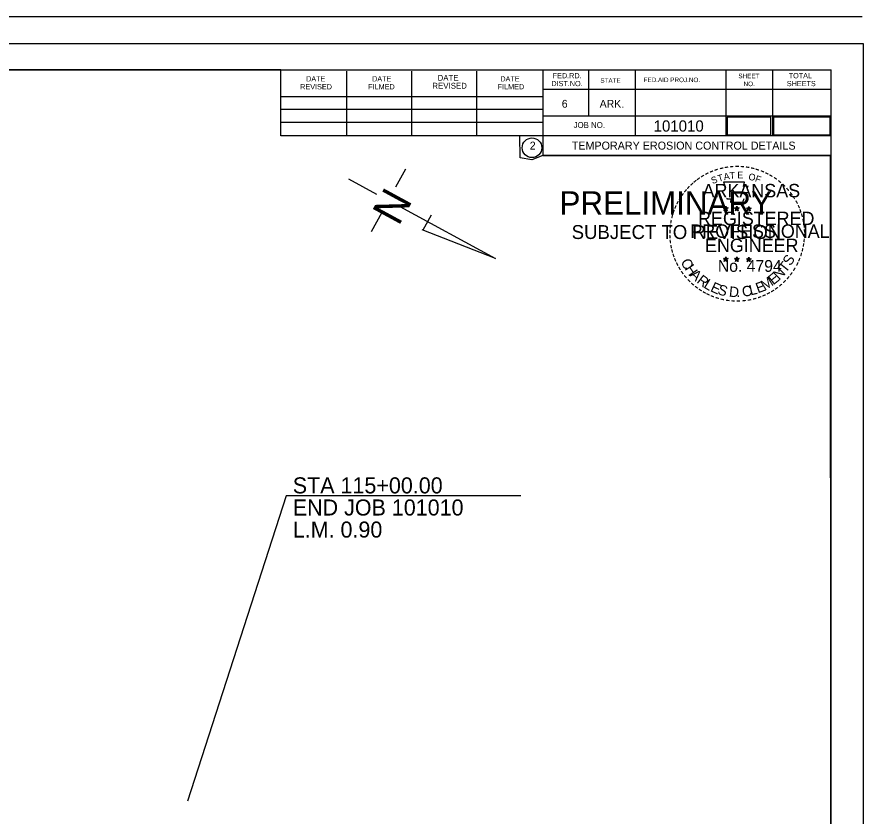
# Model space of a CAD drawing. Extents: x 7675 to 14104, y 9961 to 11168.
# Drawn here: x 9203 to 9835, y 10470 to 11067 of the extents above; entities that cross this region are included whole.
import ezdxf

# ---------------------------------------------------------------- set-up
doc = ezdxf.new("R2010")
doc.units = 0
for name, color, linetype in [('C-PSVP', 7, 'Continuous'), ('Clearing and Grubbing Ditch Checks', 7, 'Continuous'), ('Clearing and Grubbing Silt Fence', 7, 'Continuous'), ('Clearing and Grubbing Temp Seeding', 7, 'Continuous'), ('GREEN_TXT', 7, 'Continuous'), ('SEAL-INFO', 7, 'Continuous'), ('SIGNATURE', 7, 'Continuous'), ('Stage 1 Construction', 7, 'Continuous'), ('Stage 1 Ditch Checks', 7, 'Continuous')]:
    doc.layers.add(name, color=color, linetype=linetype)

msp = doc.modelspace()

# ---------------------------------------------------------------- linework, layer by layer
for p, q in [((9493.53, 10953.13), (9486.17, 10939.57)), ((9450.84, 10945.87), (9471.86, 10934.46)), ((9489.19, 10925.04), (9560.68, 10886.21)), ((9475.86, 10920.6), (9467.99, 10906.11)), ((9512.62, 10918.74), (9506.45, 10907.38)), ((9560.68, 10886.21), (9506.07, 10907.59))]:
    msp.add_line(p, q)
at = {"layer": 'C-PSVP'}
for p, q in [((9730.98, 10924.04), (9732.73, 10923.49)), ((9730.98, 10924.04), (9732.25, 10923.82)), ((9730.98, 10924.04), (9732.17, 10923.43)), ((9731.65, 10922), (9732.73, 10923.49)), ((9731.65, 10922), (9732.28, 10923.22)), ((9731.65, 10922), (9732.72, 10923.09)), ((9732.73, 10925.31), (9732.52, 10924.05)), ((9733.79, 10922), (9732.72, 10923.07)), ((9732.73, 10923.49), (9732.73, 10925.31)), ((9732.73, 10925.31), (9732.97, 10924.06)), ((9734.46, 10924.04), (9732.73, 10923.49)), ((9733.79, 10922), (9732.73, 10923.49)), ((9734.46, 10924.04), (9733.03, 10923.8)), ((9733.79, 10922), (9733.11, 10923.46)), ((9734.46, 10924.04), (9733.44, 10923.53)), ((9739.33, 10924.04), (9741.08, 10923.49)), ((9739.33, 10924.04), (9740.6, 10923.82)), ((9739.33, 10924.04), (9740.52, 10923.43)), ((9740, 10922), (9741.08, 10923.49)), ((9740, 10922), (9740.63, 10923.22)), ((9740, 10922), (9741.07, 10923.09)), ((9741.08, 10925.31), (9740.87, 10924.05)), ((9742.14, 10922), (9741.07, 10923.07)), ((9741.08, 10923.49), (9741.08, 10925.31)), ((9741.08, 10925.31), (9741.32, 10924.06)), ((9742.81, 10924.04), (9741.08, 10923.49)), ((9742.14, 10922), (9741.08, 10923.49)), ((9742.81, 10924.04), (9741.38, 10923.8)), ((9742.14, 10922), (9741.46, 10923.46)), ((9742.81, 10924.04), (9741.79, 10923.53)), ((9748.15, 10923.98), (9749.9, 10923.43)), ((9748.15, 10923.98), (9749.42, 10923.76)), ((9748.15, 10923.98), (9749.34, 10923.37)), ((9748.82, 10921.94), (9749.9, 10923.43)), ((9748.82, 10921.94), (9749.45, 10923.16)), ((9748.82, 10921.94), (9749.89, 10923.03)), ((9749.9, 10925.25), (9749.69, 10923.99)), ((9750.96, 10921.94), (9749.89, 10923.01)), ((9749.9, 10923.43), (9749.9, 10925.25)), ((9749.9, 10925.25), (9750.14, 10924)), ((9751.63, 10923.98), (9749.9, 10923.43)), ((9750.96, 10921.94), (9749.9, 10923.43)), ((9751.63, 10923.98), (9750.2, 10923.74)), ((9750.96, 10921.94), (9750.28, 10923.4)), ((9751.63, 10923.98), (9750.61, 10923.47)), ((9730.96, 10886.18), (9732.71, 10885.62)), ((9730.96, 10886.18), (9732.23, 10885.95)), ((9730.96, 10886.18), (9732.15, 10885.57)), ((9731.63, 10884.14), (9732.71, 10885.62)), ((9731.63, 10884.14), (9732.26, 10885.36)), ((9731.63, 10884.14), (9732.7, 10885.22)), ((9732.71, 10887.45), (9732.5, 10886.19)), ((9733.77, 10884.14), (9732.7, 10885.21)), ((9732.71, 10885.62), (9732.71, 10887.45)), ((9732.71, 10887.45), (9732.95, 10886.2)), ((9734.44, 10886.18), (9732.71, 10885.62)), ((9733.77, 10884.14), (9732.71, 10885.62)), ((9734.44, 10886.18), (9733.01, 10885.93)), ((9733.77, 10884.14), (9733.09, 10885.59)), ((9734.44, 10886.18), (9733.42, 10885.67)), ((9739.31, 10886.18), (9741.05, 10885.62)), ((9739.31, 10886.18), (9740.57, 10885.95)), ((9739.31, 10886.18), (9740.49, 10885.57)), ((9739.97, 10884.14), (9741.05, 10885.62)), ((9739.97, 10884.14), (9740.6, 10885.36)), ((9739.97, 10884.14), (9741.04, 10885.22)), ((9741.05, 10887.45), (9740.85, 10886.19)), ((9742.12, 10884.14), (9741.04, 10885.21)), ((9741.05, 10885.62), (9741.05, 10887.45)), ((9741.05, 10887.45), (9741.3, 10886.2)), ((9742.79, 10886.18), (9741.05, 10885.62)), ((9742.12, 10884.14), (9741.05, 10885.62)), ((9742.79, 10886.18), (9741.36, 10885.93)), ((9742.12, 10884.14), (9741.43, 10885.59)), ((9742.79, 10886.18), (9741.77, 10885.67)), ((9748.14, 10886.13), (9749.89, 10885.57)), ((9748.14, 10886.13), (9749.41, 10885.9)), ((9748.14, 10886.13), (9749.33, 10885.52)), ((9748.81, 10884.09), (9749.89, 10885.57)), ((9748.81, 10884.09), (9749.44, 10885.31)), ((9748.81, 10884.09), (9749.88, 10885.17)), ((9749.89, 10887.4), (9749.68, 10886.14)), ((9750.95, 10884.09), (9749.88, 10885.16)), ((9749.89, 10885.57), (9749.89, 10887.4)), ((9749.89, 10887.4), (9750.13, 10886.15)), ((9751.62, 10886.13), (9749.89, 10885.57)), ((9750.95, 10884.09), (9749.89, 10885.57)), ((9751.62, 10886.13), (9750.19, 10885.88)), ((9750.95, 10884.09), (9750.27, 10885.54)), ((9751.62, 10886.13), (9750.6, 10885.62))]:
    msp.add_line(p, q, dxfattribs=at)
for points in [[(9731.19, 10943.43), (9732.53, 10939.3)], [(9748.74, 10938.82), (9749.45, 10940.24), (9746.03, 10940.12), (9746.77, 10943.43), (9731.19, 10943.43)], [(9733.65, 10931.32), (9733.65, 10930.88), (9736.46, 10930.79), (9736.19, 10928.42), (9745.54, 10928.42), (9746.55, 10931.1)], [(9732.73, 10925.31), (9733.79, 10922), (9730.98, 10924.04), (9734.46, 10924.04), (9731.65, 10922), (9732.73, 10925.31)], [(9741.08, 10925.31), (9742.14, 10922), (9739.33, 10924.04), (9742.81, 10924.04), (9740, 10922), (9741.08, 10925.31)], [(9749.9, 10925.25), (9750.96, 10921.94), (9748.15, 10923.98), (9751.63, 10923.98), (9748.82, 10921.94), (9749.9, 10925.25)], [(9732.71, 10887.45), (9733.77, 10884.14), (9730.96, 10886.18), (9734.44, 10886.18), (9731.63, 10884.14), (9732.71, 10887.45)], [(9741.05, 10887.45), (9742.12, 10884.14), (9739.31, 10886.18), (9742.79, 10886.18), (9739.97, 10884.14), (9741.05, 10887.45)], [(9749.89, 10887.4), (9750.95, 10884.09), (9748.14, 10886.13), (9751.62, 10886.13), (9748.81, 10884.09), (9749.89, 10887.4)]]:
    msp.add_lwpolyline(points, dxfattribs=at)
for centre, radius in [((9732.72, 10923.48), 0.861), ((9732.72, 10923.48), 0.723), ((9732.72, 10923.48), 0.579), ((9732.72, 10923.48), 0.495), ((9732.72, 10923.48), 0.374), ((9732.72, 10923.48), 0.248), ((9732.72, 10923.48), 0.148), ((9741.07, 10923.48), 0.861), ((9741.07, 10923.48), 0.723), ((9741.07, 10923.48), 0.579), ((9741.07, 10923.48), 0.495), ((9741.07, 10923.48), 0.374), ((9741.07, 10923.48), 0.248), ((9741.07, 10923.48), 0.148), ((9749.89, 10923.42), 0.861), ((9749.89, 10923.42), 0.723), ((9749.89, 10923.42), 0.579), ((9749.89, 10923.42), 0.495), ((9749.89, 10923.42), 0.374), ((9749.89, 10923.42), 0.248), ((9749.89, 10923.42), 0.148), ((9732.7, 10885.62), 0.861), ((9732.7, 10885.62), 0.723), ((9732.7, 10885.62), 0.579), ((9732.7, 10885.62), 0.495), ((9732.7, 10885.62), 0.374), ((9732.7, 10885.62), 0.248), ((9732.7, 10885.62), 0.148), ((9741.05, 10885.62), 0.861), ((9741.05, 10885.62), 0.723), ((9741.05, 10885.62), 0.579), ((9741.05, 10885.62), 0.495), ((9741.05, 10885.62), 0.374), ((9741.05, 10885.62), 0.248), ((9741.05, 10885.62), 0.148), ((9749.88, 10885.57), 0.861), ((9749.88, 10885.57), 0.723), ((9749.88, 10885.57), 0.579), ((9749.88, 10885.57), 0.495), ((9749.88, 10885.57), 0.374), ((9749.88, 10885.57), 0.248), ((9749.88, 10885.57), 0.148)]:
    msp.add_circle(centre, radius, dxfattribs=at)
at = {"layer": 'Clearing and Grubbing Ditch Checks'}
msp.add_lwpolyline([(9733.9, 10978.65), (9766.55, 10978.65), (9766.55, 10991.85), (9733.9, 10991.85)], close=True, dxfattribs=at)
at = {"layer": 'Clearing and Grubbing Silt Fence'}
msp.add_lwpolyline([(9768.39, 10978.65), (9810.76, 10978.65), (9810.76, 10991.85), (9768.39, 10991.85)], close=True, dxfattribs=at)
at = {"layer": 'GREEN_TXT'}
for p, q in [((9834.58, 11066.7), (8074.58, 11066.7)), ((8230.68, 11027.3), (9811.58, 11027.3)), ((9400.28, 10977.9), (9400.28, 11027.3)), ((9449.58, 10977.9), (9449.58, 11026.3)), ((9498.38, 10977.9), (9498.38, 11026.3)), ((9546.78, 10977.9), (9546.78, 11026.3)), ((9596.08, 11027.3), (9596.08, 10963.3)), ((9630.28, 11027.3), (9630.28, 10992.6)), ((9664.98, 11027.3), (9664.98, 10977.9)), ((9732.88, 11027.3), (9732.88, 10977.9)), ((9767.58, 11027.3), (9767.58, 10977.9)), ((9811.58, 10000), (9811.58, 11027.3)), ((9811.58, 11012.6), (9596.08, 11012.6)), ((9811.58, 11012.7), (9811.58, 11012.7)), ((9400.28, 11007.2), (9596.08, 11007.2)), ((9400.28, 10997.9), (9596.08, 10997.9)), ((9811.58, 10992.6), (9596.08, 10992.6)), ((9400.28, 10988.2), (9596.08, 10988.2)), ((9811.58, 10977.9), (9400.28, 10977.9)), ((9596.08, 10963.3), (9811.58, 10963.3))]:
    msp.add_line(p, q, dxfattribs=at)
msp.add_circle((9588.01, 10968.98), 7.33, dxfattribs=at)
at = {"layer": 'SEAL-INFO'}
msp.add_lwpolyline([(8168.64, 11046.77), (9835.34, 11046.77), (9835.34, 9980.09), (8168.64, 9980.09)], close=True, dxfattribs=at)
at = {"layer": 'Stage 1 Construction'}
msp.add_lwpolyline([(9579.58, 10709.13), (9404.35, 10709.13), (9330.67, 10480.99)], dxfattribs=at)
at = {"layer": 'Stage 1 Ditch Checks'}
msp.add_lwpolyline([(8230.68, 10000), (9811.58, 10000), (9810.97, 10963.3), (9596.08, 10963.3), (9587.98, 10959.87), (9579.17, 10961.4), (9578.94, 10977.9), (9400.28, 10977.9), (9400.28, 11027.3), (8230.68, 11027.3)], close=True, dxfattribs=at)
msp.add_lwpolyline([(8230.68, 10000), (9811.58, 10000), (9810.97, 10963.3), (9596.08, 10963.3), (9587.98, 10959.87), (9579.17, 10961.4), (9578.94, 10977.9), (9400.28, 10977.9), (9400.28, 11027.3), (8230.68, 11027.3)], close=True, dxfattribs=at)
msp.add_lwpolyline([(8230.68, 10000), (9811.58, 10000), (9810.97, 10963.3), (9596.08, 10963.3), (9587.98, 10959.87), (9579.17, 10961.4), (9578.94, 10977.9), (9400.28, 10977.9), (9400.28, 11027.3), (8230.68, 11027.3)], close=True, dxfattribs=at)
msp.add_lwpolyline([(8230.68, 10000), (9811.58, 10000), (9810.97, 10963.3), (9596.08, 10963.3), (9587.98, 10959.87), (9579.17, 10961.4), (9578.94, 10977.9), (9400.28, 10977.9), (9400.28, 11027.3), (8230.68, 11027.3)], close=True, dxfattribs=at)
msp.add_lwpolyline([(8230.68, 10000), (9811.58, 10000), (9810.97, 10963.3), (9596.08, 10963.3), (9587.98, 10959.87), (9579.17, 10961.4), (9578.94, 10977.9), (9400.28, 10977.9), (9400.28, 11027.3), (8230.68, 11027.3)], close=True, dxfattribs=at)

# ---------------------------------------------------------------- texts
msp.add_text('N', height=23.27, rotation=241.48958).set_placement((9478.67, 10940.8))
at = {"layer": 'C-PSVP'}
for s, height, rotation, p in [('-', 8, 13.63015, (9728.68, 10950.27)), ('-', 8, 10.21935, (9732.07, 10951.08)), ('-', 8, 5.89682, (9735.71, 10951.63)), ('-', 8, 0.18623, (9739.57, 10951.99)), ('-', 8, 357.74304, (9743.19, 10951.93)), ('-', 8, 352.16172, (9746.91, 10951.65)), ('-', 8, 347.20489, (9750.5, 10951.08)), ('-', 8, 34.06357, (9715.61, 10944.29)), ('-', 8, 28.79182, (9718.59, 10946.14)), ('-', 8, 24.30721, (9721.76, 10947.72)), ('S', 5, 21.59401, (9722.96, 10941.82)), ('-', 8, 19.17608, (9724.93, 10949.07)), ('T', 5, 16.4036, (9727.53, 10943.48)), ('A', 5, 11.21318, (9731.66, 10944.73)), ('T', 5, 6.02276, (9735.91, 10945.56)), ('E', 5, 0.83234, (9741.43, 10946.11)), ('O', 5, 350.4515, (9749.45, 10945.06)), ('F', 5, 340.07066, (9754.22, 10943.92)), ('-', 8, 342.3362, (9753.68, 10950.3)), ('-', 8, 337.85509, (9757.35, 10949.19)), ('-', 8, 334.12109, (9760.51, 10947.83)), ('-', 8, 329.64089, (9763.4, 10946.42)), ('-', 8, 42.96224, (9708.17, 10938.34)), ('-', 8, 38.95066, (9710.34, 10940.42)), ('-', 8, 36.23174, (9712.72, 10942.31)), ('-', 8, 325.86266, (9766.62, 10944.61)), ('-', 8, 320.52971, (9769.67, 10942.48)), ('-', 8, 315.57859, (9772.66, 10940.04)), ('-', 8, 54.23247, (9701.85, 10930.68)), ('-', 8, 50.61417, (9703.92, 10933.52)), ('-', 8, 48.42305, (9705.93, 10935.95)), ('-', 8, 309.87973, (9775.51, 10937.29)), ('-', 8, 306.65218, (9778.13, 10934.28)), ('-', 8, 62.87135, (9698.66, 10924.98)), ('-', 8, 58.07063, (9700.23, 10928.05)), ('-', 7, 303.67529, (9780.56, 10931.44)), ('-', 8, 299.66835, (9782.16, 10928.41)), ('-', 8, 72.39447, (9696.27, 10918.77)), ('-', 8, 67.77427, (9697.37, 10921.92)), ('-', 8, 294.66279, (9783.78, 10925.35)), ('-', 8, 290.57283, (9785.06, 10922.46)), ('-', 8, 75.46096, (9695.29, 10915.2)), ('-', 8, 285.12326, (9786.23, 10919.56)), ('-', 8, 280.54934, (9787.23, 10915.85)), ('-', 8, 85.18634, (9694.25, 10908.18)), ('-', 8, 81.20126, (9694.63, 10911.64)), ('-', 8, 276.59616, (9788.04, 10912.01)), ('-', 8, 94.19588, (9694.3, 10901.05)), ('-', 8, 89.06224, (9694.12, 10904.68)), ('-', 8, 274.33011, (9788.34, 10908.4)), ('-', 8, 269.94067, (9788.51, 10905.24)), ('-', 8, 98.94793, (9694.66, 10897.72)), ('-', 8, 260.99529, (9788.06, 10898.64)), ('-', 8, 263.5172, (9788.42, 10901.91)), ('-', 8, 101.71495, (9695.33, 10894.05)), ('-', 8, 105.45785, (9696.14, 10891.08)), ('-', 8, 255.7626, (9787.51, 10895.25)), ('-', 8, 109.08742, (9697.22, 10887.92)), ('-', 8, 114.06432, (9698.49, 10884.94)), ('C', 7.7, 296.9133, (9698.85, 10883.9)), ('T', 7.7, 51.51144, (9777.52, 10875.07)), ('S', 7.7, 57.878, (9781.17, 10880.28)), ('-', 8, 247.88866, (9785.49, 10888.29)), ('-', 8, 255.7626, (9786.55, 10891.81)), ('-', 8, 115.72885, (9700.01, 10881.85)), ('-', 8, 120.44712, (9701.8, 10878.92)), ('H', 7.7, 303.27986, (9701.81, 10878.7)), ('N', 7.7, 45.14487, (9772.72, 10869.86)), ('-', 8, 239.07125, (9782.21, 10881.38)), ('-', 8, 244.61971, (9784.18, 10885.14)), ('-', 8, 125.89344, (9703.81, 10876.12)), ('-', 8, 130.71812, (9706.12, 10873.36)), ('A', 7.7, 316.01299, (9705.45, 10873.57)), ('R', 7.7, 322.37955, (9710.57, 10868.66)), ('M', 7.7, 32.41175, (9761.88, 10862.15)), ('E', 7.7, 38.77831, (9768.28, 10866.21)), ('-', 8, 231.25377, (9778.05, 10875.29)), ('-', 8, 233.84524, (9780.2, 10878.12)), ('-', 8, 134.22381, (9708.71, 10870.63)), ('-', 8, 138.93382, (9711.33, 10868.31)), ('-', 8, 144.64634, (9714.11, 10866.28)), ('L', 7.7, 328.74612, (9715.71, 10864.91)), ('E', 7.7, 335.11268, (9720.73, 10862.12)), ('S', 7.7, 341.47924, (9726.06, 10859.96)), ('D', 7.7, 354.21237, (9734.9, 10857.9)), ('C', 7.7, 6.94549, (9745.33, 10857.71)), ('L', 7.7, 13.31206, (9751.25, 10858.66)), ('E', 7.7, 19.67862, (9756.76, 10860.26)), ('-', 8, 221.08509, (9773.05, 10869.92)), ('-', 8, 225.76533, (9775.66, 10872.47)), ('-', 8, 148.08978, (9716.92, 10864.43)), ('-', 8, 151.57039, (9719.81, 10862.8)), ('-', 8, 154.60019, (9722.42, 10861.57)), ('-', 8, 204.25161, (9761.72, 10862.3)), ('-', 8, 207.35684, (9764.84, 10863.9)), ('-', 8, 212.24909, (9767.63, 10865.63)), ('-', 8, 215.73633, (9770.3, 10867.56)), ('-', 8, 158.56121, (9725.54, 10860.3)), ('-', 8, 162.79826, (9728.98, 10859.23)), ('-', 8, 167.55551, (9732.55, 10858.41)), ('-', 8, 173.11546, (9736.41, 10857.86)), ('-', 8, 176.51827, (9740.15, 10857.6)), ('-', 8, 181.59176, (9743.87, 10857.69)), ('.', 7.7, 0.57893, (9740.76, 10857.52)), ('-', 8, 185.81666, (9747.92, 10858.07)), ('-', 8, 191.28576, (9751.6, 10858.73)), ('-', 8, 195.47429, (9755.24, 10859.73)), ('-', 8, 200.71842, (9758.63, 10860.94))]:
    msp.add_text(s, height=height, rotation=rotation, dxfattribs=at).set_placement(p)
for s, height, p in [('ARKANSAS', 10, (9715.45, 10931.99)), ('REGISTERED', 10, (9712.06, 10911.25)), ('PROFESSIONAL', 10, (9706.32, 10901.73)), ('ENGINEER', 10, (9717.26, 10891.1)), ('No. 4794', 8.785, (9726.88, 10876.35))]:
    msp.add_text(s, height=height, dxfattribs=at).set_placement(p)
at = {"layer": 'Clearing and Grubbing Temp Seeding'}
for s, height, p in [('101010', 8.4, (9678.85, 10981.05)), ('TEMPORARY EROSION CONTROL DETAILS', 6, (9617.72, 10967.6))]:
    msp.add_text(s, height=height, dxfattribs=at).set_placement(p)
at = {"layer": 'GREEN_TXT'}
for s, height, p in [('FED.RD.', 3.91, (9603.48, 11020.9)), ('SHEET', 3.42, (9742.18, 11020.9)), ('TOTAL', 3.91, (9779.78, 11020.9)), ('DATE', 3.91, (9419.28, 11018.5)), ('DATE', 3.91, (9468.58, 11018.5)), ('REVISED', 4.396, (9513.58, 11013.09)), ('DATE', 4.396, (9517.48, 11019)), ('DATE', 3.91, (9564.38, 11018.5)), ('DIST.NO.', 3.91, (9602.48, 11015)), ('STATE', 3.42, (9639.08, 11017.5)), ('FED.AID PROJ.NO.', 3.42, (9671.38, 11018)), ('NO.', 3.42, (9746.08, 11015)), ('SHEETS', 3.91, (9778.38, 11015)), ('REVISED', 3.91, (9414.88, 11012.59)), ('FILMED', 3.91, (9465.68, 11012.59)), ('FILMED', 3.91, (9562.38, 11012.59)), ('6', 5.86, (9610.28, 10998.9)), ('ARK.', 5.861, (9638.58, 10998.9)), ('JOB NO.', 4.396, (9619.08, 10983.8)), ('2', 5.86, (9586.38, 10967.69))]:
    msp.add_text(s, height=height, dxfattribs=at).set_placement(p)
at = {"layer": 'SIGNATURE'}
for s, height, p in [('PRELIMINARY', 17.5, (9608.61, 10919.01)), ('SUBJECT TO REVISION', 10.3756, (9617.65, 10900.86))]:
    msp.add_text(s, height=height, dxfattribs=at).set_placement(p)
at = {"layer": 'Stage 1 Construction'}
for s, p in [('STA 115+00.00', (9409.32, 10710.88)), ('END JOB 101010', (9409.32, 10694.38)), ('L.M. 0.90', (9409.32, 10677.88))]:
    msp.add_text(s, height=12, dxfattribs=at).set_placement(p)

doc.saveas('drawing.dxf')
